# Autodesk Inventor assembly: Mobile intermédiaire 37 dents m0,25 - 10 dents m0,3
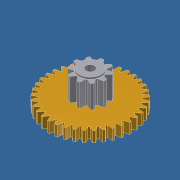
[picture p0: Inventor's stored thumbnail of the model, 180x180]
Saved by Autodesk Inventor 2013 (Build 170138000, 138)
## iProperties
Created: 2011-10
Part Number: Mobile intermédiaire 37 dents m0,25 - 10 dents m0,3
Document SubType Name: Assembly
Designer: Laur
Author: Laur
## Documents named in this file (3)
- D:\_an13-14\FORMULAIRE_2014\Sujet E4 Poissy 2014\Modélisation_7970_shimano_2014\Mobile intermédiaire 37 dents m0,25 - 10 dents m0,3.iam
- D:\_an13-14\FORMULAIRE_2014\Sujet E4 Poissy 2014\Modélisation_7970_shimano_2014\Pignon arbré creux 10 dents m0,3.ipt
- D:\_an13-14\FORMULAIRE_2014\Sujet E4 Poissy 2014\Modélisation_7970_shimano_2014\Mobile intermédiaire 37 dents m0,25 - 10 dents m0,3\Design Accelerator\Engrenages cylindriques3.iam
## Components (2 placed, 2 different names)
1. Pignon arbré creux 10 dents m0,3:1 — Placage:1, Placage:2
2. Engrenages cylindriques:1 [sub-assembly] — Placage:1, Placage:2
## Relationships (2: Mate 2)
- Placage:1 [Mate]: Pignon arbré creux 10 dents m0,3:1 ↔ Engrenages cylindriques:1
- Placage:2 [Mate]: Pignon arbré creux 10 dents m0,3:1 ↔ Engrenages cylindriques:1
